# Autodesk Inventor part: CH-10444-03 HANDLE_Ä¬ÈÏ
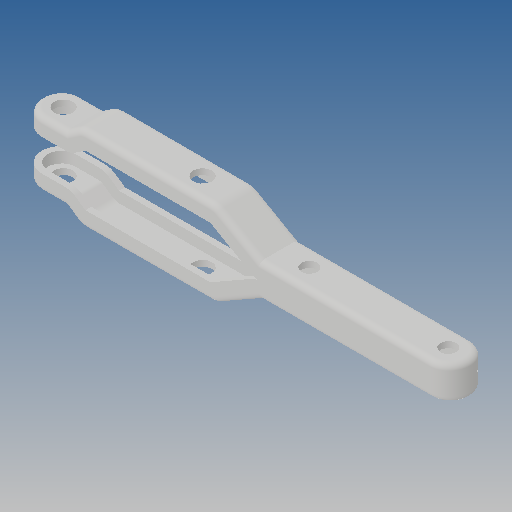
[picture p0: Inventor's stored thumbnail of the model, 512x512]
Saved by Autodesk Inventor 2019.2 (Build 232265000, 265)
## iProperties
Created: 2010-06
Part Number: CH-10444-03 HANDLE_Ä¬ÈÏ
Material: Ogólny
Document SubType Name: Modeling
Designer: CADENGINEERING4
Density: 1 g/cm^3
Appearance: Domyślna
Author: CADENGINEERING4
Revision Number: ÈÎºÎ
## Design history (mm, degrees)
feature "NONE"
feature "NONE:1"
node "Bryła1"
node "Bryła2"
